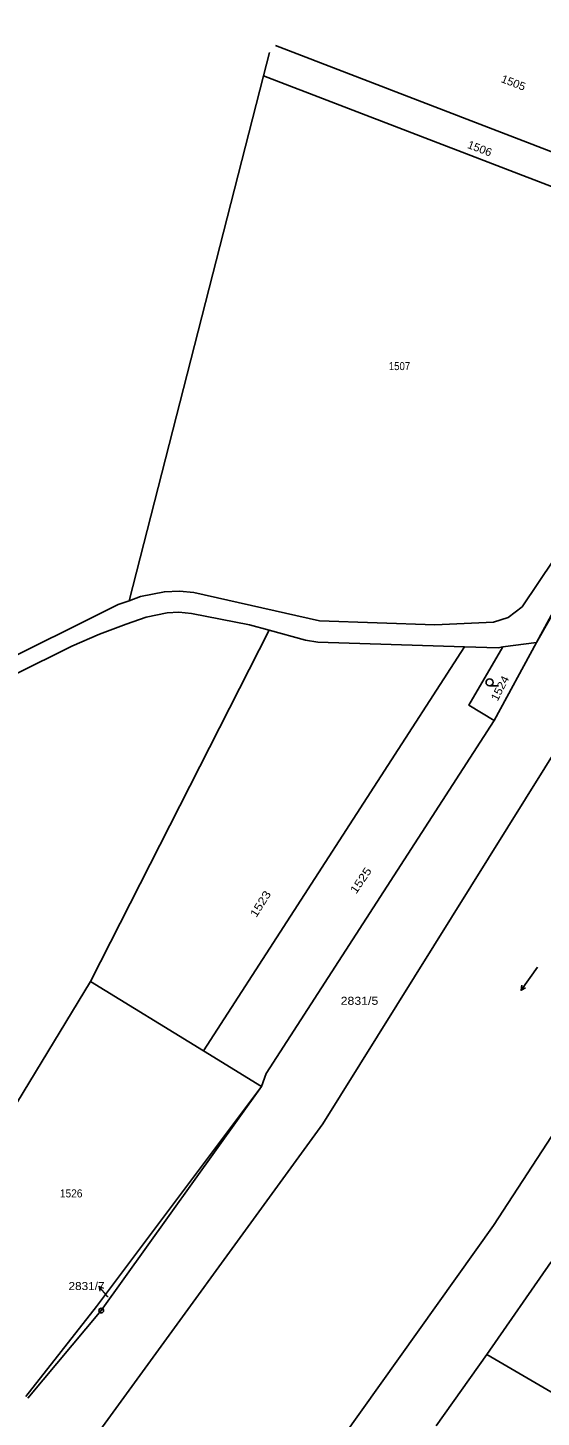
# Model space of a CAD drawing. Extents: x -546984 to -546090, y -1194931 to -1194069.
# Drawn here: x -546588.4 to -546479.3, y -1194563.2 to -1194268.1 of the extents above; entities that cross this region are included whole.
import ezdxf
from ezdxf.enums import TextEntityAlignment as Align

# ---------------------------------------------------------------- set-up
doc = ezdxf.new("R2010")
doc.units = 0
doc.header["$LTSCALE"] = 0.68
for name, color, linetype, lineweight in [('1', 7, 'Continuous', 25), ('3', 7, 'Continuous', 25), ('7', 7, 'Continuous', 13), ('8', 7, 'Continuous', 25)]:
    doc.layers.add(name, color=color, linetype=linetype, lineweight=lineweight)
doc.layers.add('2', color=7, linetype='Continuous')

msp = doc.modelspace()

# ---------------------------------------------------------------- linework, layer by layer
at = {"layer": '1'}
for p, q in [((-546535.728, -1194271.832), (-546438.82, -1194309.09)), ((-546538.28, -1194278.28), (-546566.87, -1194389.76)), ((-546489.26, -1194415.21), (-546480.28, -1194398.62)), ((-546480.28, -1194398.62), (-546487.42, -1194399.58)), ((-546551.05, -1194485.37), (-546538.72, -1194492.93))]:
    msp.add_line(p, q, dxfattribs=at)
for points in [[(-546389.24, -1194211.62), (-546383.21, -1194213.85), (-546381.43, -1194214.52), (-546374.55, -1194220.96), (-546389.16, -1194255.29), (-546392.45, -1194260.52), (-546401.16, -1194281.84), (-546427.1, -1194334), (-546466.91, -1194406.62), (-546525.73, -1194500.91), (-546575.37, -1194569.17), (-546611.42, -1194614.13), (-546654.08, -1194661.28), (-546675.45, -1194680.69), (-546700.89, -1194697.8)], [(-546480.28, -1194398.62), (-546454.62, -1194351.38), (-546441.74, -1194326.26), (-546429.78, -1194301.03), (-546417.24, -1194274.74), (-546406, -1194248.75), (-546398.33, -1194228.83), (-546392.14, -1194217.18)], [(-546392.14, -1194217.18), (-546393.03, -1194219.38), (-546404.99, -1194249.12), (-546415.92, -1194275.33), (-546428.91, -1194301.5), (-546441.35, -1194326.56), (-546453.74, -1194351.98), (-546480.28, -1194398.62)], [(-546653.83, -1194720.11), (-546626.66, -1194696.55), (-546572.27, -1194633.02), (-546541.58, -1194595.62), (-546489.43, -1194522.46), (-546452.3, -1194465.52), (-546414.56, -1194402.38), (-546384.23, -1194347.08), (-546351.57, -1194280.62), (-546352.84, -1194277.72), (-546335.99, -1194236.72), (-546326.04, -1194236.79), (-546324.23, -1194237.51), (-546321.88, -1194231.5)], [(-546537.003, -1194273.318), (-546538.28, -1194278.28), (-546441.91, -1194315.32), (-546438.82, -1194309.09)], [(-546566.87, -1194389.76), (-546564.43, -1194388.89), (-546559.37, -1194387.86), (-546556.14, -1194387.71), (-546553.09, -1194388.04), (-546526.4, -1194394.07), (-546501.89, -1194394.85), (-546489.42, -1194394.32), (-546486.31, -1194393.34), (-546483.36, -1194391.08), (-546476.54, -1194380.93), (-546446.29, -1194324.14), (-546441.91, -1194315.32)], [(-546605.25, -1194408.5), (-546575.74, -1194393.83), (-546569.16, -1194390.57), (-546566.87, -1194389.76)], [(-546537.08, -1194396.04), (-546541.3, -1194394.88), (-546553.58, -1194392.51), (-546556.28, -1194392.22), (-546558.81, -1194392.34), (-546563.23, -1194393.24), (-546567.48, -1194394.73), (-546573.16, -1194396.9), (-546579.06, -1194399.39), (-546603.46, -1194411.51), (-546612, -1194416.87), (-546621.27, -1194425.7), (-546648.92, -1194466.22), (-546661.06, -1194483.86), (-546667.68, -1194494.55), (-546669.7, -1194498.74), (-546670.46, -1194502.75), (-546669.67, -1194506.42)], [(-546669.67, -1194506.42), (-546666.91, -1194509.86), (-546658.64, -1194519.43), (-546625.89, -1194549.19), (-546615.48, -1194537.09), (-546575.06, -1194470.63), (-546537.08, -1194396.04)], [(-546495.61, -1194399.55), (-546526.76, -1194398.56), (-546529.4, -1194398.14), (-546537.08, -1194396.04)], [(-546575.06, -1194470.63), (-546551.05, -1194485.37), (-546495.61, -1194399.55)], [(-546487.42, -1194399.58), (-546488.47, -1194399.78), (-546495.61, -1194399.55)], [(-546487.42, -1194399.58), (-546494.66, -1194411.96), (-546489.26, -1194415.21)], [(-546538.72, -1194492.93), (-546537.71, -1194490.2), (-546489.26, -1194415.21)], [(-546588.84, -1194558.81), (-546573.83, -1194539.73), (-546538.72, -1194492.93)], [(-546538.72, -1194492.93), (-546572.79, -1194540.57), (-546588.42, -1194559.15)], [(-546477.14, -1194530.24), (-546490.84, -1194549.86), (-546501.59, -1194565.05)], [(-546490.84, -1194549.86), (-546462.81, -1194566.22), (-546453.83, -1194542.36)]]:
    msp.add_lwpolyline(points, dxfattribs=at)
at = {"layer": '3'}
for p, q in [((-546490.263, -1194407.86), (-546488.513, -1194407.86)), ((-546483.581, -1194472.506), (-546483.424, -1194471.418))]:
    msp.add_line(p, q, dxfattribs=at)
msp.add_lwpolyline([(-546480.112, -1194467.61), (-546483.581, -1194472.506), (-546482.607, -1194471.998)], dxfattribs=at)
msp.add_circle((-546490.2629, -1194407.1098), 0.75, dxfattribs=at)
at = {"layer": '7'}
msp.add_line((-546573.339, -1194535.355), (-546573.06, -1194536.439), dxfattribs=at)
msp.add_lwpolyline([(-546571.35, -1194537.64), (-546571.37, -1194537.62), (-546573.339, -1194535.355), (-546572.304, -1194535.782)], dxfattribs=at)
at = {"layer": '8'}
for radius in [0.5, 0.0303]:
    msp.add_circle((-546572.79, -1194540.5699), radius, dxfattribs=at)

# ---------------------------------------------------------------- texts
at = {"layer": '2'}
for s, rotation, width, p in [('1505', 339, 1.05, (-546487.974, -1194279.553)), ('1506', 339, 1.05, (-546495.134, -1194293.533)), ('1524', 63, 1.1, (-546488.572, -1194411.235)), ('1525', 56, 1.2, (-546518.615, -1194452.175)), ('1523', 58, 1.2, (-546539.843, -1194457.195))]:
    msp.add_text(s, height=1.7, rotation=rotation, dxfattribs=dict(at, width=width)).set_placement(p)
for s, width, p in [('1507', 0.9, (-546511.68, -1194340.77)), ('2831/5', 1.15, (-546521.911, -1194475.603)), ('1526', 0.95, (-546581.58, -1194516.52))]:
    msp.add_text(s, height=1.7, dxfattribs=dict(at, width=width)).set_placement(p)
at = {"layer": '2', "width": 1.1}
msp.add_text('2831/7', height=1.7, dxfattribs=at).set_placement((-546572.098, -1194536.2), align=Align.RIGHT)

doc.saveas('drawing.dxf')
